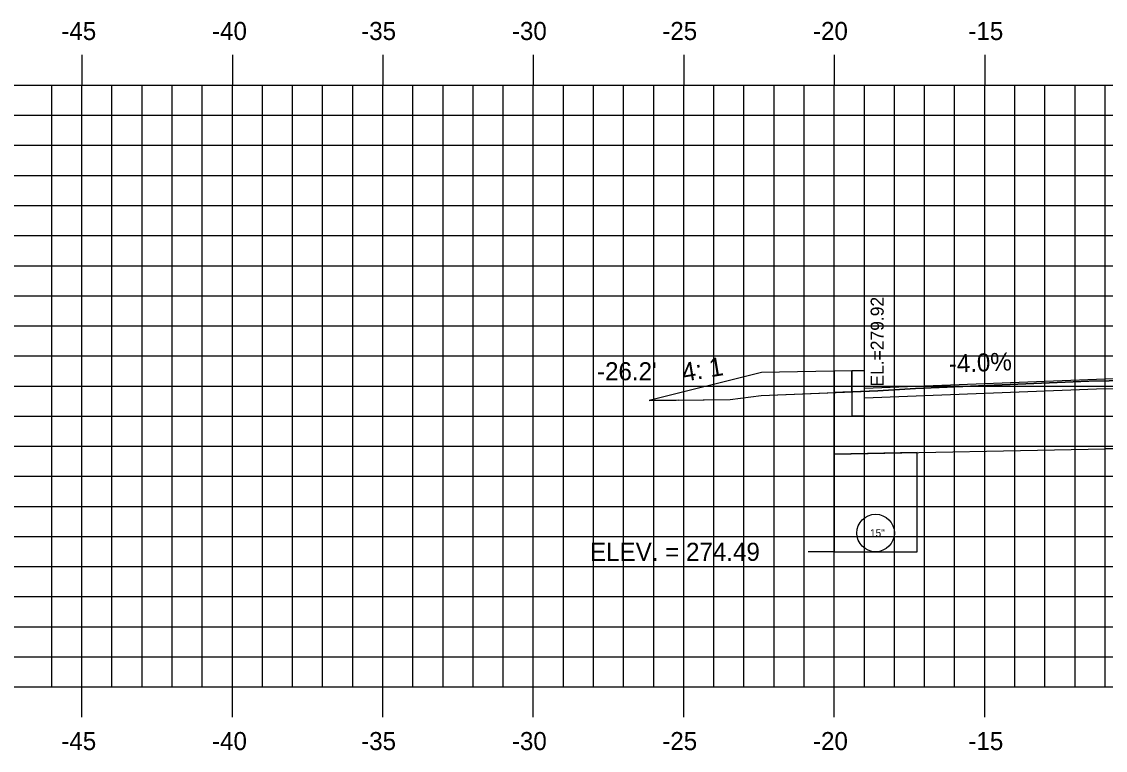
# Model space of a CAD drawing. Extents: x 853340 to 853510, y 366268 to 366378.
# Drawn here: x 853376.1 to 853412.11, y 366323.99 to 366348.21 of the extents above; entities that cross this region are included whole.
import ezdxf

# ---------------------------------------------------------------- set-up
doc = ezdxf.new("R2010")
doc.units = 0
for name, color, linetype in [('ANNOTATION', 7, 'Continuous'), ('D_Curb_Type_1_Lt', 7, 'Continuous'), ('D_Roadway_Edge_TW', 7, 'Continuous'), ('D_Roadway_FinishedGrade', 7, 'Continuous'), ('D_Roadway_SubGrade', 7, 'Continuous'), ('D_Text_Standard', 7, 'Continuous'), ('H_V ANNOTATION', 7, 'Continuous'), ('JUNK COM EXC', 7, 'Continuous'), ('JUNK FILL', 7, 'Continuous'), ('junk strct exc', 7, 'Continuous'), ('MAJOR', 7, 'Continuous'), ('MINOR', 7, 'Continuous'), ('PDRAIN', 7, 'Continuous'), ('S_Roadway_Centerline', 7, 'Continuous')]:
    doc.layers.add(name, color=color, linetype=linetype)

msp = doc.modelspace()

# ---------------------------------------------------------------- linework, layer by layer
at = {"layer": 'D_Curb_Type_1_Lt'}
msp.add_lwpolyline([(853403.683, 366336.607), (853403.683, 366335.107), (853404.1, 366335.107), (853404.1, 366336.607)], close=True, dxfattribs=at)
at = {"layer": 'D_Roadway_Edge_TW'}
msp.add_lwpolyline([(853404.1, 366336.023), (853412.1, 366336.343), (853423.1, 366336.366), (853434.1, 366336.146), (853442.099, 366335.825)], dxfattribs=at)
at = {"layer": 'D_Roadway_FinishedGrade'}
msp.add_line((853400.683, 366336.546), (853396.949, 366335.613), dxfattribs=at)
msp.add_lwpolyline([(853403.683, 366336.606), (853400.683, 366336.546)], dxfattribs=at)
at = {"layer": 'D_Roadway_SubGrade'}
for points in [[(853403.1, 366336.595), (853403.1, 366333.83)], [(853403.1, 366333.83), (853412.107, 366334.01), (853412.107, 366336.01), (853404.1, 366335.69)]]:
    msp.add_lwpolyline(points, dxfattribs=at)
msp.add_lwpolyline([(853412.107, 366334.01), (853412.107, 366336.01), (853423.107, 366336.033), (853434.107, 366335.813), (853434.107, 366333.813), (853423.107, 366334.033)], close=True, dxfattribs=at)
at = {"layer": 'D_Text_Standard'}
msp.add_lwpolyline([(853403.1, 366330.589), (853402.915, 366330.589), (853402.235, 366330.589)], dxfattribs=at)
at = {"layer": 'JUNK COM EXC'}
msp.add_lwpolyline([(853403.1, 366335.883), (853403.1, 366333.83), (853412.107, 366334.01), (853423.107, 366334.033), (853443.1, 366333.633), (853443.1, 366335.711), (853435.908, 366335.962), (853427.945, 366336.173), (853423.1, 366336.344), (853413.581, 366336.299), (853411.556, 366336.262), (853405.802, 366336.019), (853404.553, 366335.94), (853403.1, 366335.883)], dxfattribs=at)
at = {"layer": 'JUNK FILL'}
msp.add_lwpolyline([(853403.683, 366335.906), (853403.683, 366336.607), (853400.683, 366336.546), (853396.949, 366335.613), (853399.647, 366335.648), (853400.667, 366335.788)], close=True, dxfattribs=at)
at = {"layer": 'junk strct exc'}
msp.add_lwpolyline([(853403.1, 366333.83), (853403.1, 366330.589), (853405.85, 366330.589), (853405.85, 366333.885)], close=True, dxfattribs=at)
at = {"layer": 'MAJOR'}
for p, q in [((853378.1, 366347.101), (853378.1, 366346.099)), ((853383.1, 366347.101), (853383.1, 366346.099)), ((853388.1, 366347.101), (853388.1, 366346.099)), ((853393.1, 366347.101), (853393.1, 366346.099)), ((853398.1, 366347.101), (853398.1, 366346.099)), ((853403.1, 366347.101), (853403.1, 366346.099)), ((853408.1, 366347.101), (853408.1, 366346.099)), ((853353.1, 366346.099), (853493.1, 366346.099)), ((853353.1, 366346.099), (853493.1, 366346.099)), ((853378.1, 366326.099), (853378.1, 366346.099)), ((853383.1, 366326.099), (853383.1, 366346.099)), ((853388.1, 366326.099), (853388.1, 366346.099)), ((853393.1, 366326.099), (853393.1, 366346.099)), ((853398.1, 366326.099), (853398.1, 366346.099)), ((853403.1, 366326.099), (853403.1, 366346.099)), ((853408.1, 366326.099), (853408.1, 366346.099)), ((853353.1, 366341.099), (853493.1, 366341.099)), ((853353.1, 366336.099), (853493.1, 366336.099)), ((853353.1, 366331.099), (853493.1, 366331.099)), ((853353.1, 366326.099), (853493.1, 366326.099)), ((853353.1, 366326.099), (853493.1, 366326.099)), ((853378.1, 366325.097), (853378.1, 366326.099)), ((853383.1, 366325.097), (853383.1, 366326.099)), ((853388.1, 366325.097), (853388.1, 366326.099)), ((853393.1, 366325.097), (853393.1, 366326.099)), ((853398.1, 366325.097), (853398.1, 366326.099)), ((853403.1, 366325.097), (853403.1, 366326.099)), ((853408.1, 366325.097), (853408.1, 366326.099))]:
    msp.add_line(p, q, dxfattribs=at)
at = {"layer": 'MINOR'}
for p, q in [((853377.1, 366326.099), (853377.1, 366346.099)), ((853379.1, 366326.099), (853379.1, 366346.099)), ((853380.1, 366326.099), (853380.1, 366346.099)), ((853381.1, 366326.099), (853381.1, 366346.099)), ((853382.1, 366326.099), (853382.1, 366346.099)), ((853384.1, 366326.099), (853384.1, 366346.099)), ((853385.1, 366326.099), (853385.1, 366346.099)), ((853386.1, 366326.099), (853386.1, 366346.099)), ((853387.1, 366326.099), (853387.1, 366346.099)), ((853389.1, 366326.099), (853389.1, 366346.099)), ((853390.1, 366326.099), (853390.1, 366346.099)), ((853391.1, 366326.099), (853391.1, 366346.099)), ((853392.1, 366326.099), (853392.1, 366346.099)), ((853394.1, 366326.099), (853394.1, 366346.099)), ((853395.1, 366326.099), (853395.1, 366346.099)), ((853396.1, 366326.099), (853396.1, 366346.099)), ((853397.1, 366326.099), (853397.1, 366346.099)), ((853399.1, 366326.099), (853399.1, 366346.099)), ((853400.1, 366326.099), (853400.1, 366346.099)), ((853401.1, 366326.099), (853401.1, 366346.099)), ((853402.1, 366326.099), (853402.1, 366346.099)), ((853404.1, 366326.099), (853404.1, 366346.099)), ((853405.1, 366326.099), (853405.1, 366346.099)), ((853406.1, 366326.099), (853406.1, 366346.099)), ((853407.1, 366326.099), (853407.1, 366346.099)), ((853409.1, 366326.099), (853409.1, 366346.099)), ((853410.1, 366326.099), (853410.1, 366346.099)), ((853411.1, 366326.099), (853411.1, 366346.099)), ((853412.1, 366326.099), (853412.1, 366346.099)), ((853353.1, 366345.099), (853493.1, 366345.099)), ((853353.1, 366344.099), (853493.1, 366344.099)), ((853353.1, 366343.099), (853493.1, 366343.099)), ((853353.1, 366342.099), (853493.1, 366342.099)), ((853353.1, 366340.099), (853493.1, 366340.099)), ((853353.1, 366339.099), (853493.1, 366339.099)), ((853353.1, 366338.099), (853493.1, 366338.099)), ((853353.1, 366337.099), (853493.1, 366337.099)), ((853353.1, 366335.099), (853493.1, 366335.099)), ((853353.1, 366334.099), (853493.1, 366334.099)), ((853353.1, 366333.099), (853493.1, 366333.099)), ((853353.1, 366332.099), (853493.1, 366332.099)), ((853353.1, 366330.099), (853493.1, 366330.099)), ((853353.1, 366329.099), (853493.1, 366329.099)), ((853353.1, 366328.099), (853493.1, 366328.099)), ((853353.1, 366327.099), (853493.1, 366327.099))]:
    msp.add_line(p, q, dxfattribs=at)
at = {"layer": 'PDRAIN'}
msp.add_lwpolyline([(853403.1, 366333.83), (853403.1, 366330.589), (853405.85, 366330.589), (853405.85, 366333.885)], dxfattribs=at)
msp.add_circle((853404.475, 366331.214), 0.625, dxfattribs=at)
at = {"layer": 'S_Roadway_Centerline'}
msp.add_line((853397.921, 366335.625), (853396.949, 366335.613), dxfattribs=at)
msp.add_lwpolyline([(853397.921, 366335.625), (853399.647, 366335.648), (853400.667, 366335.788), (853404.553, 366335.94), (853405.802, 366336.019), (853411.556, 366336.262), (853413.581, 366336.299), (853423.1, 366336.344), (853427.945, 366336.173), (853435.908, 366335.962), (853446.195, 366335.603), (853448.746, 366335.536), (853449.861, 366335.698), (853453.832, 366335.929), (853466.982, 366336.058), (853467.693, 366336.23)], dxfattribs=at)

# ---------------------------------------------------------------- texts
at = {"layer": 'ANNOTATION'}
for s, height, rotation, p in [('-4.0%', 0.6, 2.2906, (853406.916, 366336.537)), ('4: 1', 0.6188, 9.4623, (853398.089, 366336.238))]:
    msp.add_text(s, height=height, rotation=rotation, dxfattribs=at).set_placement(p)
at = {"layer": 'D_Text_Standard'}
msp.add_text(' EL.=279.92', height=0.4335, rotation=90, dxfattribs=at).set_placement((853404.743, 366335.92))
for s, p in [("-26.2'", (853395.217, 366336.29)), ('ELEV. = 274.49', (853394.985, 366330.289))]:
    msp.add_text(s, height=0.6, dxfattribs=at).set_placement(p)
at = {"layer": 'H_V ANNOTATION'}
for s, p in [('-45', (853377.417, 366347.599)), ('-40', (853382.425, 366347.599)), ('-35', (853387.38, 366347.599)), ('-30', (853392.388, 366347.599)), ('-25', (853397.385, 366347.599)), ('-20', (853402.393, 366347.599)), ('-15', (853407.557, 366347.599)), ('-45', (853377.417, 366323.999)), ('-40', (853382.425, 366323.999)), ('-35', (853387.38, 366323.999)), ('-30', (853392.388, 366323.999)), ('-25', (853397.385, 366323.999)), ('-20', (853402.393, 366323.999)), ('-15', (853407.557, 366323.999))]:
    msp.add_text(s, height=0.6, dxfattribs=at).set_placement(p)
at = {"layer": 'PDRAIN'}
msp.add_text('15"', height=0.25, dxfattribs=at).set_placement((853404.288, 366331.089))

doc.saveas('drawing.dxf')
